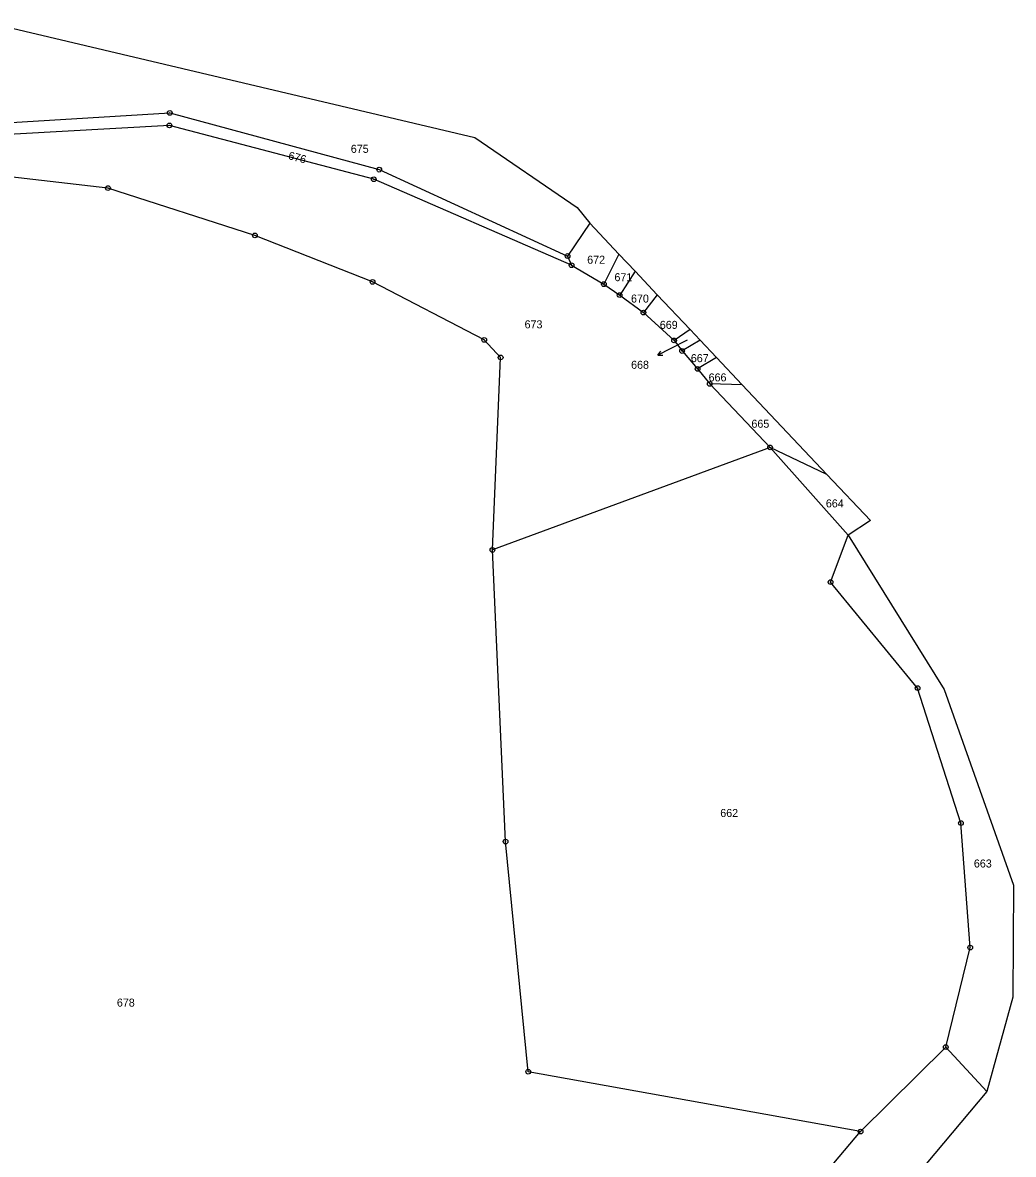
# Model space of a CAD drawing. Extents: x -783948 to -781889, y -1005870 to -1004430.
# Drawn here: x -782262.2 to -782051.8, y -1005639.6 to -1005399.2 of the extents above; entities that cross this region are included whole.
import ezdxf

# ---------------------------------------------------------------- set-up
doc = ezdxf.new("R2010")
doc.units = 0
for name, color, linetype in [('Vrstva 1', 7, 'Continuous'), ('Vrstva 2', 7, 'Continuous'), ('Vrstva 7', 7, 'Continuous'), ('Vrstva 8', 7, 'Continuous')]:
    doc.layers.add(name, color=color, linetype=linetype)

msp = doc.modelspace()

# ---------------------------------------------------------------- linework, layer by layer
at = {"layer": 'Vrstva 1'}
for p, q in [((-782144.44, -1005438.47), (-782141.73, -1005441.84)), ((-782141.73, -1005441.84), (-782146.48, -1005448.8)), ((-782141.73, -1005441.84), (-782135.55, -1005448.4)), ((-782146.48, -1005448.8), (-782145.62, -1005450.75)), ((-782135.55, -1005448.4), (-782138.75, -1005454.78)), ((-782135.55, -1005448.4), (-782132.11, -1005452.04)), ((-782145.62, -1005450.75), (-782138.75, -1005454.78)), ((-782132.11, -1005452.04), (-782135.4, -1005457.09)), ((-782132.11, -1005452.04), (-782127.4, -1005457.04)), ((-782138.75, -1005454.78), (-782135.4, -1005457.09)), ((-782135.4, -1005457.09), (-782130.36, -1005460.81)), ((-782127.4, -1005457.04), (-782130.36, -1005460.81)), ((-782127.4, -1005457.04), (-782120.42, -1005464.43)), ((-782130.36, -1005460.81), (-782123.85, -1005466.73)), ((-782120.42, -1005464.43), (-782123.85, -1005466.73)), ((-782120.42, -1005464.43), (-782118.33, -1005466.65)), ((-782123.85, -1005466.73), (-782122.14, -1005468.97)), ((-782118.33, -1005466.65), (-782122.14, -1005468.97)), ((-782118.33, -1005466.65), (-782114.83, -1005470.35)), ((-782122.14, -1005468.97), (-782118.84, -1005472.78)), ((-782114.83, -1005470.35), (-782118.84, -1005472.78)), ((-782114.83, -1005470.35), (-782109.37, -1005476.14)), ((-782118.84, -1005472.78), (-782116.26, -1005475.95)), ((-782109.37, -1005476.14), (-782116.26, -1005475.95)), ((-782116.26, -1005475.95), (-782103.45, -1005489.46)), ((-782109.37, -1005476.14), (-782091.41, -1005495.17)), ((-782103.45, -1005489.46), (-782162.43, -1005511.23)), ((-782086.83, -1005508.05), (-782103.45, -1005489.46)), ((-782091.41, -1005495.17), (-782103.45, -1005489.46)), ((-782091.41, -1005495.17), (-782082.14, -1005505)), ((-782082.14, -1005505), (-782086.83, -1005508.05)), ((-782084.23, -1005634.74), (-782066.13, -1005616.8)), ((-782066.13, -1005616.8), (-782057.4, -1005626.26))]:
    msp.add_line(p, q, dxfattribs=at)
for points in [[(-782269.63, -1005399.24), (-782166.16, -1005423.6), (-782144.44, -1005438.47)], [(-782277.86, -1005421.26), (-782273.98, -1005421.02), (-782230.97, -1005418.4), (-782186.48, -1005430.46), (-782146.48, -1005448.8)], [(-782145.62, -1005450.75), (-782187.63, -1005432.5), (-782231.03, -1005421.06), (-782275.42, -1005423.59)], [(-782162.43, -1005511.23), (-782160.68, -1005470.35), (-782164.17, -1005466.61), (-782187.89, -1005454.31), (-782212.88, -1005444.42), (-782244.09, -1005434.38), (-782266.8, -1005431.8)], [(-782066.13, -1005616.8), (-782060.93, -1005595.66), (-782062.9, -1005569.22), (-782072.1, -1005540.55), (-782090.59, -1005518.06), (-782086.83, -1005508.05)], [(-782086.83, -1005508.05), (-782066.5, -1005540.89), (-782051.77, -1005582.39), (-782051.91, -1005606.17), (-782057.4, -1005626.26)], [(-782084.23, -1005634.74), (-782154.82, -1005622.03), (-782159.65, -1005573.15), (-782162.43, -1005511.23)], [(-782057.4, -1005626.26), (-782101.91, -1005679.3), (-782120.63, -1005706.9), (-782141.1, -1005771.57), (-782140.87, -1005824.19)], [(-782159.05, -1005832.19), (-782154.89, -1005818.56), (-782155.75, -1005780.45), (-782152.77, -1005755.35), (-782146.18, -1005729.2), (-782132.17, -1005696.78), (-782117.42, -1005674.18), (-782084.23, -1005634.74)]]:
    msp.add_lwpolyline(points, dxfattribs=at)
at = {"layer": 'Vrstva 7'}
for p, q in [((-782121.04, -1005466.66), (-782124.65, -1005468.52)), ((-782124.65, -1005468.52), (-782127.32, -1005469.88)), ((-782127.32, -1005469.88), (-782126.66, -1005468.98)), ((-782127.32, -1005469.88), (-782126.2, -1005469.87))]:
    msp.add_line(p, q, dxfattribs=at)
at = {"layer": 'Vrstva 8'}
for centre, radius in [((-782230.97, -1005418.4), 0.5), ((-782230.97, -1005418.4), 0.0303), ((-782231.03, -1005421.06), 0.5), ((-782231.03, -1005421.06), 0.0303), ((-782186.48, -1005430.46), 0.5), ((-782186.48, -1005430.46), 0.0303), ((-782187.63, -1005432.5), 0.5), ((-782187.63, -1005432.5), 0.0303), ((-782244.09, -1005434.38), 0.5), ((-782244.09, -1005434.38), 0.0303), ((-782212.88, -1005444.42), 0.5), ((-782212.88, -1005444.42), 0.0303), ((-782146.48, -1005448.8), 0.5), ((-782146.48, -1005448.8), 0.0303), ((-782145.62, -1005450.75), 0.5), ((-782145.62, -1005450.75), 0.0303), ((-782187.89, -1005454.31), 0.5), ((-782187.89, -1005454.31), 0.0303), ((-782138.75, -1005454.78), 0.5), ((-782138.75, -1005454.78), 0.0303), ((-782135.4, -1005457.09), 0.5), ((-782135.4, -1005457.09), 0.0303), ((-782130.36, -1005460.81), 0.5), ((-782130.36, -1005460.81), 0.0303), ((-782164.17, -1005466.61), 0.5), ((-782164.17, -1005466.61), 0.0303), ((-782123.85, -1005466.73), 0.5), ((-782123.85, -1005466.73), 0.0303), ((-782122.14, -1005468.97), 0.5), ((-782122.14, -1005468.97), 0.0303), ((-782160.68, -1005470.35), 0.5), ((-782160.68, -1005470.35), 0.0303), ((-782118.84, -1005472.78), 0.5), ((-782118.84, -1005472.78), 0.0303), ((-782116.26, -1005475.95), 0.5), ((-782116.26, -1005475.95), 0.0303), ((-782103.45, -1005489.46), 0.5), ((-782103.45, -1005489.46), 0.0303), ((-782162.43, -1005511.23), 0.5), ((-782162.43, -1005511.23), 0.0303), ((-782090.59, -1005518.06), 0.5), ((-782090.59, -1005518.06), 0.0303), ((-782072.1, -1005540.55), 0.5), ((-782072.1, -1005540.55), 0.0303), ((-782062.9, -1005569.22), 0.5), ((-782062.9, -1005569.22), 0.0303), ((-782159.65, -1005573.15), 0.5), ((-782159.65, -1005573.15), 0.0303), ((-782060.93, -1005595.66), 0.5), ((-782060.93, -1005595.66), 0.0303), ((-782066.13, -1005616.8), 0.5), ((-782066.13, -1005616.8), 0.0303), ((-782154.82, -1005622.03), 0.5), ((-782154.82, -1005622.03), 0.0303), ((-782084.23, -1005634.74), 0.5), ((-782084.23, -1005634.74), 0.0303)]:
    msp.add_circle(centre, radius, dxfattribs=at)

# ---------------------------------------------------------------- texts
at = {"layer": 'Vrstva 2'}
for s, p in [('675', (-782192.51, -1005426.89)), ('672', (-782142.3, -1005450.44)), ('671', (-782136.51, -1005454.15)), ('670', (-782132.99, -1005458.69)), ('673', (-782155.6, -1005464.16)), ('669', (-782126.87, -1005464.27)), ('667', (-782120.28, -1005471.34)), ('668', (-782132.97, -1005472.75)), ('666', (-782116.51, -1005475.43)), ('665', (-782107.41, -1005485.27)), ('664', (-782091.6, -1005502.19)), ('662', (-782114.03, -1005567.93)), ('663', (-782060.16, -1005578.66)), ('678', (-782242.2, -1005608.2))]:
    msp.add_text(s, height=1.7, dxfattribs=at).set_placement(p)
msp.add_text('676', height=1.7, rotation=345, dxfattribs=at).set_placement((-782205.92, -1005428.2))

doc.saveas('drawing.dxf')
